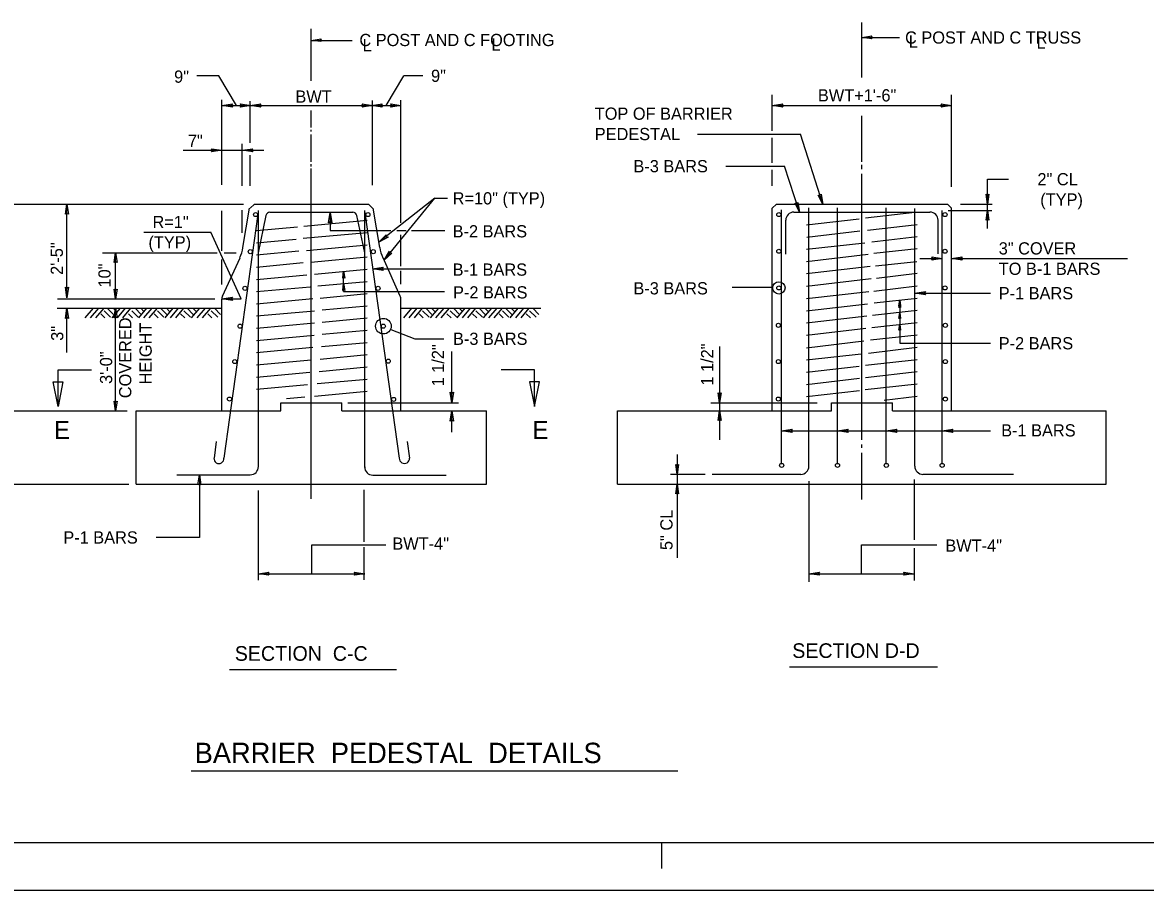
# Model space of a CAD drawing. Extents: x -3 to 26050223, y 0 to 12035012.
# Drawn here: x 21.31 to 44.29, y 0 to 17.77 of the extents above; entities that cross this region are included whole.
import ezdxf

# ---------------------------------------------------------------- set-up
doc = ezdxf.new("R2010")
doc.units = 0
for name, color, linetype in [('1', 7, 'Continuous'), ('2', 7, 'Continuous'), ('39', 7, 'Continuous')]:
    doc.layers.add(name, color=color, linetype=linetype)

msp = doc.modelspace()

# ---------------------------------------------------------------- linework, layer by layer
at = {"layer": '1'}
for p, q in [((22.591, 11.72), (22.758, 11.92)), ((22.7, 11.72), (22.866, 11.92)), ((22.808, 11.72), (22.975, 11.92)), ((22.908, 11.803), (22.991, 11.72)), ((22.975, 11.87), (23.108, 11.736)), ((23.041, 11.92), (23.166, 11.795)), ((23.141, 11.72), (23.308, 11.92)), ((23.158, 11.92), (23.225, 11.853)), ((23.25, 11.72), (23.416, 11.92)), ((23.358, 11.72), (23.525, 11.92)), ((23.475, 11.803), (23.558, 11.72)), ((23.541, 11.87), (23.675, 11.736)), ((23.608, 11.92), (23.733, 11.795)), ((23.683, 11.72), (23.85, 11.92)), ((23.725, 11.92), (23.791, 11.853)), ((23.791, 11.72), (23.958, 11.92)), ((23.9, 11.72), (24.066, 11.92)), ((24, 11.803), (24.083, 11.72)), ((24.066, 11.87), (24.2, 11.736)), ((24.133, 11.92), (24.258, 11.795)), ((24.225, 11.72), (24.391, 11.92)), ((24.25, 11.92), (24.316, 11.853)), ((24.333, 11.72), (24.5, 11.92)), ((24.441, 11.72), (24.608, 11.92)), ((24.541, 11.803), (24.625, 11.72)), ((24.608, 11.87), (24.741, 11.736)), ((24.675, 11.92), (24.8, 11.795)), ((24.766, 11.72), (24.933, 11.92)), ((24.791, 11.92), (24.858, 11.853)), ((24.883, 11.72), (25.05, 11.92)), ((24.991, 11.72), (25.158, 11.92)), ((25.1, 11.803), (25.183, 11.72)), ((25.166, 11.87), (25.3, 11.736)), ((25.233, 11.92), (25.358, 11.795)), ((29.05, 11.92), (31.916, 11.92)), ((29.108, 11.72), (29.275, 11.92)), ((29.216, 11.72), (29.383, 11.92)), ((29.325, 11.72), (29.491, 11.92)), ((29.425, 11.803), (29.508, 11.72)), ((29.491, 11.87), (29.625, 11.736)), ((29.558, 11.92), (29.683, 11.795)), ((29.658, 11.72), (29.825, 11.92)), ((29.675, 11.92), (29.741, 11.853)), ((29.766, 11.72), (29.933, 11.92)), ((29.875, 11.72), (30.041, 11.92)), ((29.991, 11.803), (30.075, 11.72)), ((30.058, 11.87), (30.191, 11.736)), ((30.125, 11.92), (30.25, 11.795)), ((30.2, 11.72), (30.366, 11.92)), ((30.241, 11.92), (30.308, 11.853)), ((30.308, 11.72), (30.475, 11.92)), ((30.416, 11.72), (30.583, 11.92)), ((30.516, 11.803), (30.6, 11.72)), ((30.583, 11.87), (30.716, 11.736)), ((30.65, 11.92), (30.775, 11.795)), ((30.741, 11.72), (30.908, 11.92)), ((30.766, 11.92), (30.833, 11.853)), ((30.85, 11.72), (31.016, 11.92)), ((30.958, 11.72), (31.125, 11.92)), ((31.058, 11.803), (31.141, 11.72)), ((31.125, 11.87), (31.258, 11.736)), ((31.191, 11.92), (31.316, 11.795)), ((31.283, 11.72), (31.45, 11.92)), ((31.308, 11.92), (31.375, 11.853)), ((31.4, 11.72), (31.566, 11.92)), ((31.508, 11.72), (31.675, 11.92)), ((31.616, 11.803), (31.7, 11.72)), ((31.683, 11.87), (31.816, 11.736)), ((31.75, 11.92), (31.875, 11.795)), ((25.541, 4.528), (28.958, 4.528)), ((37, 4.578), (40.033, 4.578)), ((3.6, 0.983), (68.183, 0.983)), ((34.392, 0.45), (34.392, 0.983)), ((68.892, 0), (0, 0))]:
    msp.add_line(p, q, dxfattribs=at)
at = {"layer": '2'}
for p, q in [((26.091, 13.511), (26.933, 13.586)), ((27.066, 13.603), (28.358, 13.72)), ((26.091, 13.261), (26.908, 13.336)), ((27.05, 13.353), (28.358, 13.47)), ((27.116, 13.103), (28.358, 13.22)), ((26.091, 13.011), (26.958, 13.095)), ((27.208, 12.861), (28.358, 12.97)), ((26.091, 12.761), (27.05, 12.853)), ((27.283, 12.62), (28.358, 12.72)), ((26.091, 12.511), (27.125, 12.603)), ((27.35, 12.378), (28.358, 12.47)), ((26.091, 12.261), (27.191, 12.361)), ((27.4, 12.128), (28.358, 12.22)), ((26.091, 12.011), (27.25, 12.12)), ((27.441, 11.886), (28.358, 11.97)), ((26.091, 11.761), (27.283, 11.87)), ((26.091, 11.511), (27.283, 11.62)), ((27.441, 11.636), (28.358, 11.72)), ((26.091, 11.261), (27.275, 11.37)), ((27.441, 11.386), (28.358, 11.47)), ((26.091, 11.011), (27.25, 11.12)), ((27.425, 11.136), (28.358, 11.22)), ((26.091, 10.761), (27.216, 10.861)), ((27.4, 10.878), (28.358, 10.97)), ((26.091, 10.511), (27.183, 10.611)), ((27.375, 10.628), (28.358, 10.72)), ((26.091, 10.261), (27.141, 10.361)), ((27.333, 10.378), (28.358, 10.47)), ((27.283, 10.12), (28.358, 10.22)), ((26.708, 10.07), (27.083, 10.103))]:
    msp.add_line(p, q, dxfattribs=at)
at = {"layer": '39'}
for p, q in [((38.483, 16.645), (38.483, 17.77)), ((27.216, 16.578), (27.216, 17.636)), ((27.216, 17.403), (28.05, 17.403)), ((38.483, 17.461), (39.25, 17.461)), ((25.325, 16.678), (24.875, 16.678)), ((25.683, 16.07), (25.325, 16.678)), ((28.75, 16.07), (29.108, 16.678)), ((29.5, 16.678), (29.108, 16.678)), ((25.383, 14.445), (25.383, 16.186)), ((25.966, 16.07), (25.966, 16.161)), ((28.466, 14.436), (28.466, 16.17)), ((29.05, 13.67), (29.05, 16.178)), ((36.65, 15.553), (36.65, 16.286)), ((40.316, 14.403), (40.316, 16.286)), ((25.383, 16.07), (25.975, 16.07)), ((25.966, 16.07), (28.466, 16.07)), ((25.966, 15.303), (25.966, 16.053)), ((27.216, 15.62), (27.216, 15.97)), ((28.45, 16.07), (29.05, 16.07)), ((36.65, 16.07), (40.316, 16.07)), ((38.483, 14.92), (38.483, 15.861)), ((27.216, 15.536), (27.216, 15.57)), ((27.216, 14.92), (27.216, 15.478)), ((35.116, 15.486), (37.225, 15.486)), ((36.65, 14.895), (36.65, 15.411)), ((37.683, 14.053), (37.225, 15.486)), ((25.8, 15.17), (25.8, 15.286)), ((24.591, 15.153), (25.383, 15.153)), ((25.366, 15.153), (25.8, 15.153)), ((25.8, 14.428), (25.8, 15.153)), ((25.8, 15.153), (26.241, 15.153)), ((25.966, 14.428), (25.966, 15.053)), ((27.216, 14.82), (27.216, 14.87)), ((27.216, 8.02), (27.216, 14.778)), ((35.7, 14.828), (36.9, 14.828)), ((36.65, 14.428), (36.65, 14.753)), ((37.208, 13.886), (36.9, 14.828)), ((38.483, 14.77), (38.483, 14.853)), ((38.483, 9.228), (38.483, 14.67)), ((41.05, 14.053), (41.05, 14.561)), ((41.05, 14.561), (41.483, 14.561)), ((20.775, 14.053), (25.825, 14.053)), ((22.216, 12.136), (22.216, 14.053)), ((25.966, 13.97), (26.05, 14.053)), ((26.05, 14.053), (28.383, 14.053)), ((28.466, 13.97), (28.383, 14.053)), ((29.741, 14.17), (28.6, 13.27)), ((28.708, 12.903), (29.741, 14.17)), ((29.741, 14.17), (30, 14.17)), ((36.65, 13.97), (36.733, 14.053)), ((36.733, 14.053), (40.233, 14.053)), ((40.316, 13.97), (40.233, 14.053)), ((40.5, 14.053), (41.15, 14.053)), ((41.05, 13.92), (41.05, 14.053)), ((25.383, 13.095), (25.383, 13.911)), ((26.125, 13.845), (25.425, 8.853)), ((25.8, 13.461), (25.8, 13.928)), ((25.816, 13.161), (25.95, 13.97)), ((26.133, 8.678), (26.133, 13.92)), ((26.133, 13.053), (26.291, 13.82)), ((26.366, 13.886), (28.066, 13.886)), ((27.6, 13.878), (27.6, 13.511)), ((28.308, 13.053), (28.15, 13.82)), ((28.308, 8.661), (28.308, 13.92)), ((28.308, 13.878), (29.016, 8.853)), ((28.616, 13.161), (28.483, 13.97)), ((36.65, 9.82), (36.65, 13.97)), ((36.841, 8.745), (36.841, 13.936)), ((37.091, 13.886), (39.875, 13.886)), ((37.4, 8.686), (37.4, 13.978)), ((37.983, 8.745), (37.983, 13.978)), ((38.558, 13.77), (39.566, 13.886)), ((38.983, 8.745), (38.983, 13.978)), ((39.566, 8.686), (39.566, 13.961)), ((40.125, 8.745), (40.125, 13.92)), ((40.25, 13.92), (41.141, 13.92)), ((40.316, 9.82), (40.316, 13.97)), ((41.05, 13.553), (41.05, 13.92)), ((36.925, 13.028), (36.925, 13.72)), ((37.35, 13.628), (38.425, 13.753)), ((38.6, 13.52), (39.616, 13.636)), ((40.041, 13.036), (40.041, 13.72)), ((23.791, 13.478), (25.158, 13.478)), ((25.783, 12.111), (25.158, 13.478)), ((27.6, 13.511), (28.841, 13.511)), ((28.966, 13.511), (29.158, 13.511)), ((29.05, 12.778), (29.05, 13.42)), ((29.266, 13.511), (29.95, 13.511)), ((37.358, 13.378), (38.441, 13.503)), ((38.683, 13.278), (39.616, 13.386)), ((37.35, 13.128), (38.541, 13.261)), ((38.725, 13.045), (39.616, 13.145)), ((22.941, 13.053), (25.291, 13.053)), ((23.208, 12.111), (23.208, 13.053)), ((25.383, 12.403), (25.383, 12.92)), ((25.4, 12.17), (25.758, 12.953)), ((25.433, 13.053), (25.675, 13.053)), ((28.633, 13.053), (28.633, 13.053)), ((29.033, 12.17), (28.683, 12.953)), ((37.35, 12.878), (38.608, 13.028)), ((38.758, 12.786), (39.608, 12.878)), ((39.666, 12.936), (40.125, 12.936)), ((40.316, 12.936), (43.916, 12.936)), ((27.875, 12.42), (27.875, 12.678)), ((28.466, 12.728), (29.925, 12.728)), ((29.05, 12.411), (29.05, 12.686)), ((37.35, 12.628), (38.65, 12.778)), ((27.875, 12.261), (27.875, 12.428)), ((37.35, 12.37), (38.675, 12.528)), ((38.783, 12.536), (39.616, 12.636)), ((27.875, 12.261), (29.941, 12.261)), ((36.666, 12.345), (35.825, 12.345)), ((37.35, 12.12), (38.625, 12.261)), ((38.725, 12.27), (39.616, 12.378)), ((39.566, 12.228), (41.116, 12.228)), ((22.025, 12.111), (25.241, 12.111)), ((25.383, 12.111), (25.783, 12.111)), ((25.383, 9.82), (25.383, 12.103)), ((29.05, 9.82), (29.05, 12.103)), ((37.35, 11.87), (38.6, 12.011)), ((38.733, 12.028), (39.616, 12.128)), ((39.258, 12.086), (39.258, 11.82)), ((22.016, 11.92), (25.391, 11.92)), ((22.216, 11.011), (22.216, 11.92)), ((23.208, 9.82), (23.208, 11.92)), ((37.35, 11.62), (38.583, 11.761)), ((38.7, 11.778), (39.616, 11.878)), ((39.258, 11.828), (39.258, 11.586)), ((37.35, 11.37), (38.566, 11.511)), ((38.683, 11.528), (39.616, 11.628)), ((39.258, 11.586), (39.258, 11.203)), ((28.841, 11.486), (29.333, 11.295)), ((29.333, 11.295), (29.925, 11.295)), ((38.658, 11.27), (39.616, 11.378)), ((30.091, 9.986), (30.091, 11.036)), ((35.566, 11.136), (35.566, 9.986)), ((37.35, 11.111), (38.525, 11.253)), ((38.616, 11.003), (39.616, 11.12)), ((39.258, 11.203), (41.116, 11.203)), ((37.35, 10.861), (38.466, 10.986)), ((38.558, 10.753), (39.616, 10.87)), ((22.033, 9.936), (22.033, 10.661)), ((22.033, 10.661), (22.716, 10.661)), ((31.783, 10.661), (31.1, 10.661)), ((31.783, 9.936), (31.783, 10.661)), ((37.35, 10.611), (38.425, 10.736)), ((38.558, 10.503), (39.616, 10.628)), ((22.033, 9.911), (21.933, 10.411)), ((21.933, 10.411), (22.133, 10.411)), ((22.033, 9.911), (21.933, 10.411)), ((21.933, 10.411), (22.133, 10.411)), ((22.133, 10.411), (22.033, 9.911)), ((22.133, 10.411), (22.033, 9.911)), ((31.883, 10.411), (31.683, 10.411)), ((31.683, 10.411), (31.783, 9.911)), ((31.683, 10.411), (31.783, 9.911)), ((31.883, 10.411), (31.683, 10.411)), ((31.783, 9.911), (31.883, 10.411)), ((31.783, 9.911), (31.883, 10.411)), ((37.35, 10.361), (38.433, 10.486)), ((38.55, 10.253), (39.616, 10.37)), ((37.35, 10.111), (38.433, 10.236)), ((38.941, 10.036), (39.616, 10.12)), ((26.591, 9.986), (27.841, 9.986)), ((26.591, 9.82), (26.591, 9.986)), ((27.841, 9.82), (27.841, 9.986)), ((27.966, 9.986), (30.225, 9.986)), ((35.391, 9.986), (37.566, 9.986)), ((35.566, 9.986), (35.566, 9.82)), ((37.858, 9.82), (37.858, 9.986)), ((37.858, 9.986), (39.108, 9.986)), ((39.108, 9.82), (39.108, 9.986)), ((20.741, 9.82), (23.45, 9.82)), ((23.633, 8.32), (23.633, 9.82)), ((23.633, 9.82), (26.591, 9.82)), ((27.841, 9.82), (30.8, 9.82)), ((30.091, 9.386), (30.091, 9.82)), ((30.8, 8.32), (30.8, 9.82)), ((33.483, 8.32), (33.483, 9.82)), ((33.483, 9.82), (37.858, 9.82)), ((35.566, 9.82), (35.566, 9.228)), ((39.108, 9.82), (43.483, 9.82)), ((43.483, 8.32), (43.483, 9.82)), ((25.266, 9.195), (25.225, 8.853)), ((29.175, 9.195), (29.225, 8.853)), ((36.841, 9.411), (38, 9.411)), ((37.983, 9.411), (38.983, 9.411)), ((38.983, 9.411), (40.108, 9.411)), ((40.125, 9.411), (41.116, 9.411)), ((38.483, 9.061), (38.483, 9.128)), ((34.7, 8.928), (34.7, 8.52)), ((38.483, 8.003), (38.483, 8.961)), ((24.466, 8.511), (25.966, 8.511)), ((24.925, 8.511), (24.925, 7.228)), ((34.566, 8.52), (35.275, 8.52)), ((34.7, 8.52), (34.7, 8.32)), ((35.416, 8.52), (37.233, 8.52)), ((39.733, 8.52), (41.583, 8.52)), ((20.725, 8.32), (23.483, 8.32)), ((23.633, 8.32), (30.8, 8.32)), ((28.475, 8.503), (29.975, 8.503)), ((33.483, 8.32), (43.483, 8.32)), ((34.7, 8.32), (34.7, 6.811)), ((37.4, 8.378), (37.4, 6.32)), ((39.55, 8.411), (39.55, 7.178)), ((26.133, 6.353), (26.133, 8.186)), ((28.3, 7.136), (28.3, 8.203)), ((24.925, 7.228), (24.041, 7.228)), ((27.225, 7.078), (28.741, 7.078)), ((27.225, 6.486), (27.225, 7.078)), ((28.3, 6.361), (28.3, 7.028)), ((38.475, 6.486), (38.475, 7.078)), ((38.475, 7.078), (40.016, 7.078)), ((39.55, 7.011), (39.55, 6.345)), ((26.133, 6.486), (28.308, 6.486)), ((37.4, 6.486), (39.55, 6.486)), ((24.754, 2.451), (34.713, 2.451))]:
    msp.add_line(p, q, dxfattribs=at)
for points in [[(38.666, 17.461), (38.683, 17.436), (38.483, 17.461), (38.683, 17.495)], [(38.666, 17.461), (38.683, 17.436), (38.483, 17.461), (38.683, 17.495)], [(27.4, 17.403), (27.416, 17.378), (27.216, 17.403), (27.416, 17.436)], [(27.4, 17.403), (27.416, 17.378), (27.216, 17.403), (27.416, 17.436)], [(25.575, 16.07), (25.6, 16.036), (25.383, 16.07), (25.6, 16.103)], [(25.783, 16.07), (25.766, 16.103), (25.975, 16.07), (25.766, 16.036)], [(26.158, 16.07), (26.183, 16.036), (25.966, 16.07), (26.183, 16.103)], [(28.275, 16.07), (28.258, 16.103), (28.466, 16.07), (28.258, 16.036)], [(28.641, 16.07), (28.666, 16.036), (28.45, 16.07), (28.666, 16.103)], [(28.858, 16.07), (28.841, 16.103), (29.05, 16.07), (28.841, 16.036)], [(36.841, 16.07), (36.866, 16.036), (36.65, 16.07), (36.866, 16.103)], [(40.125, 16.07), (40.108, 16.103), (40.316, 16.07), (40.108, 16.036)], [(25.191, 15.153), (25.175, 15.186), (25.383, 15.153), (25.175, 15.12)], [(25.991, 15.153), (26.016, 15.12), (25.8, 15.153), (26.016, 15.186)], [(37.625, 14.228), (37.65, 14.253), (37.683, 14.053), (37.591, 14.236)], [(41.05, 14.236), (41.083, 14.253), (41.05, 14.053), (41.025, 14.253)], [(22.216, 13.861), (22.183, 13.845), (22.216, 14.053), (22.25, 13.845)], [(37.15, 14.061), (37.175, 14.086), (37.208, 13.886), (37.116, 14.07)], [(37.15, 14.061), (37.175, 14.086), (37.208, 13.886), (37.116, 14.07)], [(27.6, 13.686), (27.566, 13.67), (27.6, 13.878), (27.633, 13.67)], [(41.05, 13.736), (41.025, 13.72), (41.05, 13.92), (41.083, 13.72)], [(41.05, 13.736), (41.025, 13.72), (41.05, 13.92), (41.083, 13.72)], [(28.75, 13.386), (28.791, 13.378), (28.6, 13.27), (28.75, 13.42)], [(23.208, 12.87), (23.183, 12.853), (23.208, 13.053), (23.241, 12.853)], [(28.833, 13.053), (28.866, 13.045), (28.708, 12.903), (28.816, 13.086)], [(39.933, 12.936), (39.916, 12.97), (40.125, 12.936), (39.916, 12.903)], [(40.508, 12.936), (40.533, 12.903), (40.316, 12.936), (40.533, 12.97)], [(27.875, 12.553), (27.858, 12.536), (27.875, 12.678), (27.9, 12.536)], [(28.658, 12.728), (28.683, 12.695), (28.466, 12.728), (28.683, 12.761)], [(27.875, 12.303), (27.858, 12.286), (27.875, 12.428), (27.9, 12.286)], [(22.216, 12.328), (22.25, 12.353), (22.216, 12.136), (22.183, 12.353)], [(23.208, 12.295), (23.241, 12.311), (23.208, 12.111), (23.183, 12.311)], [(23.208, 12.295), (23.241, 12.311), (23.208, 12.111), (23.183, 12.311)], [(39.758, 12.228), (39.783, 12.195), (39.566, 12.228), (39.783, 12.261)], [(25.575, 12.111), (25.6, 12.078), (25.383, 12.111), (25.6, 12.145)], [(39.258, 11.986), (39.241, 11.97), (39.258, 12.086), (39.275, 11.97)], [(39.258, 11.986), (39.241, 11.97), (39.258, 12.086), (39.275, 11.97)], [(39.258, 11.953), (39.241, 11.936), (39.258, 12.053), (39.275, 11.936)], [(22.216, 11.728), (22.183, 11.711), (22.216, 11.92), (22.25, 11.711)], [(23.208, 11.736), (23.183, 11.72), (23.208, 11.92), (23.241, 11.72)], [(39.258, 11.728), (39.241, 11.711), (39.258, 11.828), (39.275, 11.711)], [(39.258, 11.486), (39.241, 11.47), (39.258, 11.586), (39.275, 11.47)], [(30.091, 10.178), (30.125, 10.203), (30.091, 9.986), (30.058, 10.203)], [(35.566, 10.17), (35.6, 10.186), (35.566, 9.986), (35.541, 10.186)], [(23.208, 10.003), (23.241, 10.02), (23.208, 9.82), (23.183, 10.02)], [(30.091, 9.628), (30.058, 9.611), (30.091, 9.82), (30.125, 9.611)], [(35.566, 9.636), (35.541, 9.62), (35.566, 9.82), (35.6, 9.62)], [(35.566, 9.636), (35.541, 9.62), (35.566, 9.82), (35.6, 9.62)], [(37.033, 9.411), (37.058, 9.378), (36.841, 9.411), (37.058, 9.445)], [(38.175, 9.411), (38.2, 9.378), (37.983, 9.411), (38.2, 9.445)], [(39.175, 9.411), (39.2, 9.378), (38.983, 9.411), (39.2, 9.445)], [(40.316, 9.411), (40.341, 9.378), (40.125, 9.411), (40.341, 9.445)], [(24.925, 8.32), (24.891, 8.303), (24.925, 8.511), (24.958, 8.303)], [(34.7, 8.703), (34.733, 8.72), (34.7, 8.52), (34.675, 8.72)], [(34.7, 8.703), (34.733, 8.72), (34.7, 8.52), (34.675, 8.72)], [(34.7, 8.136), (34.675, 8.12), (34.7, 8.32), (34.733, 8.12)], [(26.325, 6.486), (26.35, 6.453), (26.133, 6.486), (26.35, 6.52)], [(28.116, 6.486), (28.1, 6.52), (28.308, 6.486), (28.1, 6.453)], [(37.591, 6.486), (37.616, 6.453), (37.4, 6.486), (37.616, 6.52)], [(39.358, 6.486), (39.341, 6.52), (39.55, 6.486), (39.341, 6.453)]]:
    msp.add_lwpolyline(points, close=True, dxfattribs=at)
for centre, radius in [((26.075, 13.836), 0.0417), ((28.375, 13.836), 0.0417), ((36.783, 13.836), 0.0417), ((40.183, 13.836), 0.0417), ((25.966, 13.078), 0.0417), ((28.483, 13.078), 0.0417), ((36.783, 13.086), 0.0417), ((40.183, 13.086), 0.0417), ((36.783, 12.336), 0.127), ((25.858, 12.328), 0.0417), ((28.583, 12.328), 0.0417), ((36.783, 12.336), 0.0417), ((40.183, 12.336), 0.0417), ((25.758, 11.553), 0.0417), ((28.691, 11.553), 0.16), ((28.691, 11.553), 0.0417), ((36.775, 11.57), 0.0417), ((40.191, 11.57), 0.0417), ((25.65, 10.828), 0.0417), ((28.791, 10.836), 0.0417), ((36.775, 10.828), 0.0417), ((40.191, 10.828), 0.0417), ((25.541, 10.061), 0.0417), ((28.9, 10.053), 0.0417), ((36.775, 10.061), 0.0417), ((40.191, 10.061), 0.0417), ((36.841, 8.703), 0.0417), ((37.983, 8.703), 0.0417), ((38.983, 8.703), 0.0417), ((40.125, 8.703), 0.0417)]:
    msp.add_circle(centre, radius, dxfattribs=at)
for centre, radius, start, end in [((26.37, 13.803), 0.0833, 90, 170.5377), ((28.066, 13.803), 0.0833, 12.5288, 90), ((37.091, 13.72), 0.167, 90, 180), ((39.875, 13.72), 0.167, 0, 90), ((24.997, 13.301), 0.833, 335.556, 350.1342), ((29.437, 13.3), 0.833, 189.4623, 204.7024), ((25.55, 12.101), 0.167, 156.0375, 180), ((28.883, 12.101), 0.167, 0, 23.9625), ((25.325, 8.842), 0.101, 173.7808, 6.2192), ((29.121, 8.847), 0.104, 176.6542, 3.3458), ((25.966, 8.678), 0.167, 270, 0), ((28.475, 8.67), 0.167, 180, 270), ((37.233, 8.686), 0.167, 270, 0), ((39.733, 8.686), 0.167, 180, 270)]:
    msp.add_arc(centre, radius, start, end, dxfattribs=at)

# ---------------------------------------------------------------- texts
at = {"layer": '1'}
for p in [(21.95, 9.245), (31.741, 9.245)]:
    msp.add_text('E', height=0.367, dxfattribs=at).set_placement(p)
at = {"layer": '2'}
for s, p in [('C POST AND C FOOTING', (28.2, 17.286)), ('C POST AND C TRUSS', (39.366, 17.336)), ('L', (39.441, 17.253)), ('L', (42.058, 17.236)), ('L', (28.266, 17.178)), ('L', (30.9, 17.195)), ('9"', (24.408, 16.536)), ('9"', (29.666, 16.553)), ('BWT', (26.891, 16.128)), ('BWT+1\'-6"', (37.583, 16.153)), ('TOP OF BARRIER', (33.016, 15.778)), ('7"', (24.691, 15.22)), ('PEDESTAL', (33.016, 15.361)), ('B-3 BARS', (33.808, 14.703)), ('2" CL', (42.075, 14.436)), ('R=10" (TYP)', (30.108, 14.045)), ('(TYP)', (42.133, 14.02)), ('R=1"', (23.966, 13.561)), ('B-2 BARS', (30.108, 13.37)), ('(TYP)', (23.883, 13.145)), ('3" COVER', (41.283, 13.02)), ('B-1 BARS', (30.108, 12.586)), ('TO B-1 BARS', (41.283, 12.603)), ('B-3 BARS', (33.808, 12.203)), ('P-2 BARS', (30.116, 12.12)), ('P-1 BARS', (41.283, 12.103)), ('B-3 BARS', (30.116, 11.17)), ('P-2 BARS', (41.283, 11.078)), ('B-1 BARS', (41.333, 9.295)), ('P-1 BARS', (22.141, 7.103)), ('BWT-4"', (28.875, 6.978)), ('BWT-4"', (40.191, 6.936))]:
    msp.add_text(s, height=0.25, dxfattribs=at).set_placement(p)
for s, p in [('2\'-5"', (22.133, 12.603)), ('10"', (23.108, 12.345)), ('3"', (22.141, 11.253)), ('COVERED ', (23.533, 10.078)), ('HEIGHT', (23.95, 10.361)), ('1 1/2"', (35.441, 10.336)), ('3\'-0"', (23.141, 10.37)), ('5" CL', (34.608, 6.97))]:
    msp.add_text(s, height=0.25, rotation=90, dxfattribs=at).set_placement(p)
at = {"layer": '39'}
msp.add_text('1 1/2"', height=0.25, rotation=90, dxfattribs=at).set_placement((29.933, 10.32))
for s, height, p in [('SECTION D-D', 0.3, (37.058, 4.761)), ('SECTION  C-C', 0.3, (25.65, 4.703)), ('BARRIER  PEDESTAL  DETAILS', 0.41665, (24.829, 2.609))]:
    msp.add_text(s, height=height, dxfattribs=at).set_placement(p)

doc.saveas('drawing.dxf')
